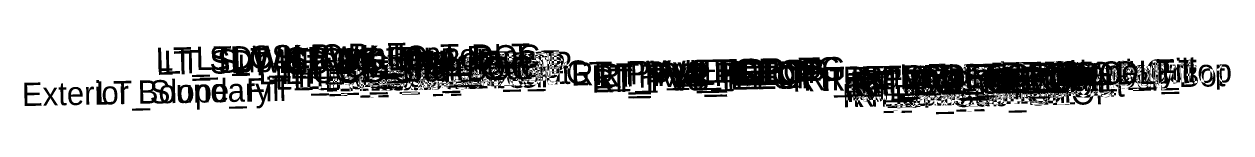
# Model space of a CAD drawing. Extents: x 118 to 4243, y 0 to 9511.
# Drawn here: x 3141.1 to 3244.9, y 9503 to 9509.2 of the extents above; entities that cross this region are included whole.
import ezdxf

# ---------------------------------------------------------------- set-up
doc = ezdxf.new("R2010")
doc.units = 0
doc.layers.add('Scratch_Level_0', color=7, linetype='Continuous')

msp = doc.modelspace()

# ---------------------------------------------------------------- texts
at = {"layer": 'Scratch_Level_0'}
for s, p in [('LT_SDWK_Out_Top', (3152.46, 9506.73)), ('LT_Sub_Trench_Out_DLT', (3153.14, 9506.48)), ('LT_CSLP_Pnt', (3155.9, 9506.81)), ('LT_SDWK_In_Top', (3159.08, 9506.67)), ('LT_CG_Top_Face', (3162.99, 9506.56)), ('LT_CG_Top_BOC', (3163.51, 9506.58)), ('LT_SDWK_Out_Bot', (3152.49, 9506.4)), ('LT_SDWK_In_Bot', (3159.11, 9506.33)), ('LT_CG1_Shelf_Out', (3161.28, 9505.58)), ('LT_CG_Bot_BOC', (3163.54, 9505.6)), ('LT_CG_Top_Gut', (3163.97, 9506.08)), ('LT_PV2_OEEOP', (3167.04, 9505.87)), ('LT_PV3_OEEOP', (3167.04, 9505.54)), ('LT_PV1_OEEOP', (3167.6, 9506.01)), ('LT_CG_Bot_IE', (3167.64, 9505.55)), ('LT_PV2_OEOT', (3167.9, 9505.89)), ('LT_PV3_OEOT', (3167.9, 9505.56)), ('LT_PV1_OEOT', (3168.47, 9506.15)), ('RT_PV_IEEOP_EG', (3188.16, 9505.48)), ('LT_PV_IEEOP_EG', (3188.21, 9505.48)), ('RT_Slope_Fill', (3225.07, 9505.46)), ('LT_PV_Sub_Tie_Out', (3162.69, 9505.12)), ('LT_Sub_OEOP', (3164.27, 9505.08)), ('LT_PV_OEEOP_EG', (3165.27, 9505.17)), ('LT_Sub_OEEOP', (3166.94, 9504.96)), ('LT_Sub_OEOT', (3167.81, 9504.97)), ('RT_PV2_IEEOP', (3189.93, 9505.22)), ('RT_PV3_IEEOP', (3189.93, 9504.88)), ('LT_PV2_IEEOP', (3189.97, 9505.22)), ('LT_PV3_IEEOP', (3189.97, 9504.89)), ('RT_PV1_IEEOP', (3190.49, 9505.35)), ('LT_PV1_IEEOP', (3190.54, 9505.35)), ('PV2_PGL', (3193.93, 9505.3)), ('PV1_PGL', (3194.49, 9505.56)), ('RT_PV_Sub_Tie_Out', (3207.2, 9504.96)), ('RT_Sub_Trench_Out_DLT', (3208.13, 9505.03)), ('RT_PV_OEEOP_EG', (3209.81, 9505.02)), ('RT_CG_Top_Face', (3211.53, 9505.11)), ('RT_PV2_OEEOP', (3211.58, 9504.54)), ('RT_PV1_OEEOP', (3212.14, 9504.67)), ('RT_PV2_OEOT', (3212.44, 9504.55)), ('RT_CG_Top_Gut', (3212.51, 9504.62)), ('RT_PV1_OEOT', (3213.01, 9504.81)), ('RT_CG_Top_BOC', (3213.05, 9505.13)), ('RT_SDWK_In_Top', (3216.63, 9505.21)), ('RT_SDWK_In_Bot', (3216.67, 9504.87)), ('Exterior Boundary', (3218.74, 9505.33)), ('RT_SDWK_Out_Top', (3220.01, 9505.27)), ('RT_SDWK_Out_Bot', (3220.04, 9504.94)), ('RT_Slope_Cut', (3224.19, 9505.44)), ('RT_CSLP_Pnt', (3224.44, 9505.35)), ('Exterior Boundary', (3140.95, 9503.72)), ('LT_Slope_Fill', (3147.32, 9503.84)), ('RT_Sub_OEEOP', (3211.48, 9503.62)), ('RT_PV3_OEEOP', (3211.58, 9504.2)), ('RT_CG1_Shelf_Out', (3211.82, 9504.06)), ('RT_CG_Bot_IE', (3212.18, 9504.21)), ('RT_Sub_OEOT', (3212.35, 9503.63)), ('RT_PV3_OEOT', (3212.44, 9504.22)), ('RT_CG_Bot_BOC', (3213.08, 9504.11)), ('RT_Sub_OEOP', (3215.98, 9503.53))]:
    msp.add_text(s, height=2, rotation=1.1458, dxfattribs=at).set_placement(p)

doc.saveas('drawing.dxf')
